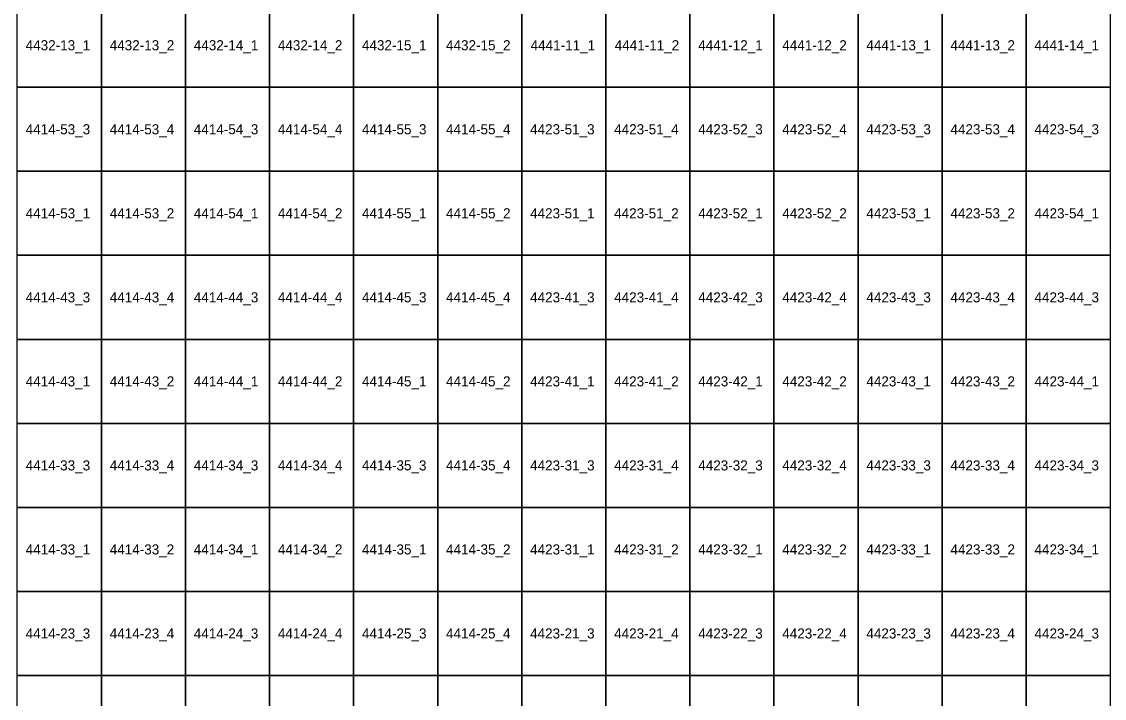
# Model space of a CAD drawing. Extents: x 312500 to 765000, y 172500 to 440000.
# Drawn here: x 635129 to 667325, y 331819 to 351952 of the extents above; entities that cross this region are included whole.
import ezdxf

# ---------------------------------------------------------------- set-up
doc = ezdxf.new("R2010")
doc.units = 0
doc.layers.add('Topo5_ramis_TKS2025', color=7, linetype='Continuous')
doc.layers.add('Topo5_ramis_TKS2025_Nr', color=7, linetype='Continuous')

msp = doc.modelspace()

# ---------------------------------------------------------------- linework, layer by layer
at = {"layer": 'Topo5_ramis_TKS2025'}
for points in [[(635000, 350000), (635000, 352500), (637500, 352500), (637500, 350000), (635000, 350000)], [(637500, 350000), (637500, 352500), (640000, 352500), (640000, 350000), (637500, 350000)], [(640000, 350000), (640000, 352500), (642500, 352500), (642500, 350000), (640000, 350000)], [(642500, 350000), (642500, 352500), (645000, 352500), (645000, 350000), (642500, 350000)], [(645000, 350000), (645000, 352500), (647500, 352500), (647500, 350000), (645000, 350000)], [(647500, 350000), (647500, 352500), (650000, 352500), (650000, 350000), (647500, 350000)], [(650000, 350000), (650000, 352500), (652500, 352500), (652500, 350000), (650000, 350000)], [(652500, 350000), (652500, 352500), (655000, 352500), (655000, 350000), (652500, 350000)], [(655000, 350000), (655000, 352500), (657500, 352500), (657500, 350000), (655000, 350000)], [(657500, 350000), (657500, 352500), (660000, 352500), (660000, 350000), (657500, 350000)], [(660000, 350000), (660000, 352500), (662500, 352500), (662500, 350000), (660000, 350000)], [(662500, 350000), (662500, 352500), (665000, 352500), (665000, 350000), (662500, 350000)], [(665000, 350000), (665000, 352500), (667500, 352500), (667500, 350000), (665000, 350000)], [(635000, 347500), (635000, 350000), (637500, 350000), (637500, 347500), (635000, 347500)], [(637500, 347500), (637500, 350000), (640000, 350000), (640000, 347500), (637500, 347500)], [(640000, 347500), (640000, 350000), (642500, 350000), (642500, 347500), (640000, 347500)], [(642500, 347500), (642500, 350000), (645000, 350000), (645000, 347500), (642500, 347500)], [(645000, 347500), (645000, 350000), (647500, 350000), (647500, 347500), (645000, 347500)], [(647500, 347500), (647500, 350000), (650000, 350000), (650000, 347500), (647500, 347500)], [(650000, 347500), (650000, 350000), (652500, 350000), (652500, 347500), (650000, 347500)], [(652500, 347500), (652500, 350000), (655000, 350000), (655000, 347500), (652500, 347500)], [(655000, 347500), (655000, 350000), (657500, 350000), (657500, 347500), (655000, 347500)], [(657500, 347500), (657500, 350000), (660000, 350000), (660000, 347500), (657500, 347500)], [(660000, 347500), (660000, 350000), (662500, 350000), (662500, 347500), (660000, 347500)], [(662500, 347500), (662500, 350000), (665000, 350000), (665000, 347500), (662500, 347500)], [(665000, 347500), (665000, 350000), (667500, 350000), (667500, 347500), (665000, 347500)], [(635000, 345000), (635000, 347500), (637500, 347500), (637500, 345000), (635000, 345000)], [(637500, 345000), (637500, 347500), (640000, 347500), (640000, 345000), (637500, 345000)], [(640000, 345000), (640000, 347500), (642500, 347500), (642500, 345000), (640000, 345000)], [(642500, 345000), (642500, 347500), (645000, 347500), (645000, 345000), (642500, 345000)], [(645000, 345000), (645000, 347500), (647500, 347500), (647500, 345000), (645000, 345000)], [(647500, 345000), (647500, 347500), (650000, 347500), (650000, 345000), (647500, 345000)], [(650000, 345000), (650000, 347500), (652500, 347500), (652500, 345000), (650000, 345000)], [(652500, 345000), (652500, 347500), (655000, 347500), (655000, 345000), (652500, 345000)], [(655000, 345000), (655000, 347500), (657500, 347500), (657500, 345000), (655000, 345000)], [(657500, 345000), (657500, 347500), (660000, 347500), (660000, 345000), (657500, 345000)], [(660000, 345000), (660000, 347500), (662500, 347500), (662500, 345000), (660000, 345000)], [(662500, 345000), (662500, 347500), (665000, 347500), (665000, 345000), (662500, 345000)], [(665000, 345000), (665000, 347500), (667500, 347500), (667500, 345000), (665000, 345000)], [(635000, 342500), (635000, 345000), (637500, 345000), (637500, 342500), (635000, 342500)], [(637500, 342500), (637500, 345000), (640000, 345000), (640000, 342500), (637500, 342500)], [(640000, 342500), (640000, 345000), (642500, 345000), (642500, 342500), (640000, 342500)], [(642500, 342500), (642500, 345000), (645000, 345000), (645000, 342500), (642500, 342500)], [(645000, 342500), (645000, 345000), (647500, 345000), (647500, 342500), (645000, 342500)], [(647500, 342500), (647500, 345000), (650000, 345000), (650000, 342500), (647500, 342500)], [(650000, 342500), (650000, 345000), (652500, 345000), (652500, 342500), (650000, 342500)], [(652500, 342500), (652500, 345000), (655000, 345000), (655000, 342500), (652500, 342500)], [(655000, 342500), (655000, 345000), (657500, 345000), (657500, 342500), (655000, 342500)], [(657500, 342500), (657500, 345000), (660000, 345000), (660000, 342500), (657500, 342500)], [(660000, 342500), (660000, 345000), (662500, 345000), (662500, 342500), (660000, 342500)], [(662500, 342500), (662500, 345000), (665000, 345000), (665000, 342500), (662500, 342500)], [(665000, 342500), (665000, 345000), (667500, 345000), (667500, 342500), (665000, 342500)], [(635000, 340000), (635000, 342500), (637500, 342500), (637500, 340000), (635000, 340000)], [(637500, 340000), (637500, 342500), (640000, 342500), (640000, 340000), (637500, 340000)], [(640000, 340000), (640000, 342500), (642500, 342500), (642500, 340000), (640000, 340000)], [(642500, 340000), (642500, 342500), (645000, 342500), (645000, 340000), (642500, 340000)], [(645000, 340000), (645000, 342500), (647500, 342500), (647500, 340000), (645000, 340000)], [(647500, 340000), (647500, 342500), (650000, 342500), (650000, 340000), (647500, 340000)], [(650000, 340000), (650000, 342500), (652500, 342500), (652500, 340000), (650000, 340000)], [(652500, 340000), (652500, 342500), (655000, 342500), (655000, 340000), (652500, 340000)], [(655000, 340000), (655000, 342500), (657500, 342500), (657500, 340000), (655000, 340000)], [(657500, 340000), (657500, 342500), (660000, 342500), (660000, 340000), (657500, 340000)], [(660000, 340000), (660000, 342500), (662500, 342500), (662500, 340000), (660000, 340000)], [(662500, 340000), (662500, 342500), (665000, 342500), (665000, 340000), (662500, 340000)], [(665000, 340000), (665000, 342500), (667500, 342500), (667500, 340000), (665000, 340000)], [(635000, 337500), (635000, 340000), (637500, 340000), (637500, 337500), (635000, 337500)], [(637500, 337500), (637500, 340000), (640000, 340000), (640000, 337500), (637500, 337500)], [(640000, 337500), (640000, 340000), (642500, 340000), (642500, 337500), (640000, 337500)], [(642500, 337500), (642500, 340000), (645000, 340000), (645000, 337500), (642500, 337500)], [(645000, 337500), (645000, 340000), (647500, 340000), (647500, 337500), (645000, 337500)], [(647500, 337500), (647500, 340000), (650000, 340000), (650000, 337500), (647500, 337500)], [(650000, 337500), (650000, 340000), (652500, 340000), (652500, 337500), (650000, 337500)], [(652500, 337500), (652500, 340000), (655000, 340000), (655000, 337500), (652500, 337500)], [(655000, 337500), (655000, 340000), (657500, 340000), (657500, 337500), (655000, 337500)], [(657500, 337500), (657500, 340000), (660000, 340000), (660000, 337500), (657500, 337500)], [(660000, 337500), (660000, 340000), (662500, 340000), (662500, 337500), (660000, 337500)], [(662500, 337500), (662500, 340000), (665000, 340000), (665000, 337500), (662500, 337500)], [(665000, 337500), (665000, 340000), (667500, 340000), (667500, 337500), (665000, 337500)], [(635000, 335000), (635000, 337500), (637500, 337500), (637500, 335000), (635000, 335000)], [(637500, 335000), (637500, 337500), (640000, 337500), (640000, 335000), (637500, 335000)], [(640000, 335000), (640000, 337500), (642500, 337500), (642500, 335000), (640000, 335000)], [(642500, 335000), (642500, 337500), (645000, 337500), (645000, 335000), (642500, 335000)], [(645000, 335000), (645000, 337500), (647500, 337500), (647500, 335000), (645000, 335000)], [(647500, 335000), (647500, 337500), (650000, 337500), (650000, 335000), (647500, 335000)], [(650000, 335000), (650000, 337500), (652500, 337500), (652500, 335000), (650000, 335000)], [(652500, 335000), (652500, 337500), (655000, 337500), (655000, 335000), (652500, 335000)], [(655000, 335000), (655000, 337500), (657500, 337500), (657500, 335000), (655000, 335000)], [(657500, 335000), (657500, 337500), (660000, 337500), (660000, 335000), (657500, 335000)], [(660000, 335000), (660000, 337500), (662500, 337500), (662500, 335000), (660000, 335000)], [(662500, 335000), (662500, 337500), (665000, 337500), (665000, 335000), (662500, 335000)], [(665000, 335000), (665000, 337500), (667500, 337500), (667500, 335000), (665000, 335000)], [(635000, 332500), (635000, 335000), (637500, 335000), (637500, 332500), (635000, 332500)], [(637500, 332500), (637500, 335000), (640000, 335000), (640000, 332500), (637500, 332500)], [(640000, 332500), (640000, 335000), (642500, 335000), (642500, 332500), (640000, 332500)], [(642500, 332500), (642500, 335000), (645000, 335000), (645000, 332500), (642500, 332500)], [(645000, 332500), (645000, 335000), (647500, 335000), (647500, 332500), (645000, 332500)], [(647500, 332500), (647500, 335000), (650000, 335000), (650000, 332500), (647500, 332500)], [(650000, 332500), (650000, 335000), (652500, 335000), (652500, 332500), (650000, 332500)], [(652500, 332500), (652500, 335000), (655000, 335000), (655000, 332500), (652500, 332500)], [(655000, 332500), (655000, 335000), (657500, 335000), (657500, 332500), (655000, 332500)], [(657500, 332500), (657500, 335000), (660000, 335000), (660000, 332500), (657500, 332500)], [(660000, 332500), (660000, 335000), (662500, 335000), (662500, 332500), (660000, 332500)], [(662500, 332500), (662500, 335000), (665000, 335000), (665000, 332500), (662500, 332500)], [(665000, 332500), (665000, 335000), (667500, 335000), (667500, 332500), (665000, 332500)], [(635000, 330000), (635000, 332500), (637500, 332500), (637500, 330000), (635000, 330000)], [(637500, 330000), (637500, 332500), (640000, 332500), (640000, 330000), (637500, 330000)], [(640000, 330000), (640000, 332500), (642500, 332500), (642500, 330000), (640000, 330000)], [(642500, 330000), (642500, 332500), (645000, 332500), (645000, 330000), (642500, 330000)], [(645000, 330000), (645000, 332500), (647500, 332500), (647500, 330000), (645000, 330000)], [(647500, 330000), (647500, 332500), (650000, 332500), (650000, 330000), (647500, 330000)], [(650000, 330000), (650000, 332500), (652500, 332500), (652500, 330000), (650000, 330000)], [(652500, 330000), (652500, 332500), (655000, 332500), (655000, 330000), (652500, 330000)], [(655000, 330000), (655000, 332500), (657500, 332500), (657500, 330000), (655000, 330000)], [(657500, 330000), (657500, 332500), (660000, 332500), (660000, 330000), (657500, 330000)], [(660000, 330000), (660000, 332500), (662500, 332500), (662500, 330000), (660000, 330000)], [(662500, 330000), (662500, 332500), (665000, 332500), (665000, 330000), (662500, 330000)], [(665000, 330000), (665000, 332500), (667500, 332500), (667500, 330000), (665000, 330000)]]:
    msp.add_lwpolyline(points, dxfattribs=at)

# ---------------------------------------------------------------- texts
at = {"layer": 'Topo5_ramis_TKS2025_Nr'}
for s, p in [('4432-13_1', (635248, 351100)), ('4432-13_2', (637748, 351100)), ('4432-14_1', (640248, 351100)), ('4432-14_2', (642748, 351100)), ('4432-15_1', (645248, 351100)), ('4432-15_2', (647748, 351100)), ('4441-11_1', (650264, 351100)), ('4441-11_2', (652764, 351100)), ('4441-12_1', (655248, 351100)), ('4441-12_2', (657748, 351100)), ('4441-13_1', (660248, 351100)), ('4441-13_2', (662748, 351100)), ('4441-14_1', (665248, 351100)), ('4414-53_3', (635248, 348600)), ('4414-53_4', (637748, 348600)), ('4414-54_3', (640248, 348600)), ('4414-54_4', (642748, 348600)), ('4414-55_3', (645248, 348600)), ('4414-55_4', (647748, 348600)), ('4423-51_3', (650248, 348600)), ('4423-51_4', (652748, 348600)), ('4423-52_3', (655248, 348600)), ('4423-52_4', (657748, 348600)), ('4423-53_3', (660248, 348600)), ('4423-53_4', (662748, 348600)), ('4423-54_3', (665248, 348600)), ('4414-53_1', (635248, 346100)), ('4414-53_2', (637748, 346100)), ('4414-54_1', (640248, 346100)), ('4414-54_2', (642748, 346100)), ('4414-55_1', (645248, 346100)), ('4414-55_2', (647748, 346100)), ('4423-51_1', (650248, 346100)), ('4423-51_2', (652748, 346100)), ('4423-52_1', (655248, 346100)), ('4423-52_2', (657748, 346100)), ('4423-53_1', (660248, 346100)), ('4423-53_2', (662748, 346100)), ('4423-54_1', (665248, 346100)), ('4414-43_3', (635248, 343600)), ('4414-43_4', (637748, 343600)), ('4414-44_3', (640248, 343600)), ('4414-44_4', (642748, 343600)), ('4414-45_3', (645248, 343600)), ('4414-45_4', (647748, 343600)), ('4423-41_3', (650248, 343600)), ('4423-41_4', (652748, 343600)), ('4423-42_3', (655248, 343600)), ('4423-42_4', (657748, 343600)), ('4423-43_3', (660248, 343600)), ('4423-43_4', (662748, 343600)), ('4423-44_3', (665248, 343600)), ('4414-43_1', (635248, 341100)), ('4414-43_2', (637748, 341100)), ('4414-44_1', (640248, 341100)), ('4414-44_2', (642748, 341100)), ('4414-45_1', (645248, 341100)), ('4414-45_2', (647748, 341100)), ('4423-41_1', (650248, 341100)), ('4423-41_2', (652748, 341100)), ('4423-42_1', (655248, 341100)), ('4423-42_2', (657748, 341100)), ('4423-43_1', (660248, 341100)), ('4423-43_2', (662748, 341100)), ('4423-44_1', (665248, 341100)), ('4414-33_3', (635248, 338600)), ('4414-33_4', (637748, 338600)), ('4414-34_3', (640248, 338600)), ('4414-34_4', (642748, 338600)), ('4414-35_3', (645248, 338600)), ('4414-35_4', (647748, 338600)), ('4423-31_3', (650248, 338600)), ('4423-31_4', (652748, 338600)), ('4423-32_3', (655248, 338600)), ('4423-32_4', (657748, 338600)), ('4423-33_3', (660248, 338600)), ('4423-33_4', (662748, 338600)), ('4423-34_3', (665248, 338600)), ('4414-33_1', (635248, 336100)), ('4414-33_2', (637748, 336100)), ('4414-34_1', (640248, 336100)), ('4414-34_2', (642748, 336100)), ('4414-35_1', (645248, 336100)), ('4414-35_2', (647748, 336100)), ('4423-31_1', (650248, 336100)), ('4423-31_2', (652748, 336100)), ('4423-32_1', (655248, 336100)), ('4423-32_2', (657748, 336100)), ('4423-33_1', (660248, 336100)), ('4423-33_2', (662748, 336100)), ('4423-34_1', (665248, 336100)), ('4414-23_3', (635248, 333600)), ('4414-23_4', (637748, 333600)), ('4414-24_3', (640248, 333600)), ('4414-24_4', (642748, 333600)), ('4414-25_3', (645248, 333600)), ('4414-25_4', (647748, 333600)), ('4423-21_3', (650248, 333600)), ('4423-21_4', (652748, 333600)), ('4423-22_3', (655248, 333600)), ('4423-22_4', (657748, 333600)), ('4423-23_3', (660248, 333600)), ('4423-23_4', (662748, 333600)), ('4423-24_3', (665248, 333600))]:
    msp.add_text(s, height=300, dxfattribs=at).set_placement(p)

doc.saveas('drawing.dxf')
